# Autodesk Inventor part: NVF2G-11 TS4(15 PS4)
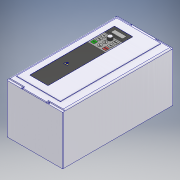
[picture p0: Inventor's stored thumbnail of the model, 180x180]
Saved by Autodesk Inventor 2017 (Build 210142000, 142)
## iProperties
Part Number: NVF2G-11 TS4(15 PS4)
Material: Типовые
Document SubType Name: Modeling
Designer: RSagdiev
Density: 1 g/cm^3
Appearance: По умолчанию
Author: RSagdiev
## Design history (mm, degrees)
sketch "Эскиз1"
  geometry: L1 (0, 0)-(44.679, 0) reference; L2 (0, 0)-(0, 56.035) reference; L3 (0, 0)-(378, 0); L4 (378, 0)-(378, 167.6); L5 (378, 167.6)-(0, 167.6); L6 (0, 167.6)-(0, 0)
  constraints: 12 end point, 3 horizontal, 2 parallel, 2 vertical, 1 perpendicular
  dimensions: "d0" = 378 distance of L5.end L4.end; "d1" = 167.6 distance of L4.end L3.end
extrude "Выдавливание1" new body sketch "Эскиз1" stored distance "d2" = 191; taper "d3" = 0 deg
sketch "Эскиз2"
  geometry: L1 (0, 0)-(0, 378) reference; L2 (191, 0)-(191, 378) reference; L3 (0, 378)-(55, 378); L4 (191, 378)-(191, 371); L5 (191, 0)-(136, 0); L6 (0, 0)-(0, 7); L7 (0, 378)-(191, 378) reference; L8 (0, 378)-(55, 378); L9 (55, 378)-(55, 371); L10 (55, 371)-(0, 371); L11 (0, 371)-(0, 378); L12 (191, 378)-(136, 378); L13 (136, 378)-(136, 371); L14 (136, 371)-(191, 371); L15 (191, 371)-(191, 378); L16 (0, 0)-(191, 0) reference; L17 (0, 0)-(55, 0); L18 (55, 0)-(55, 7); L19 (55, 7)-(0, 7); L20 (0, 7)-(0, 0); L21 (191, 0)-(136, 0); L22 (136, 0)-(136, 7); L23 (136, 7)-(191, 7); L24 (191, 7)-(191, 0); L25 (55, 378)-(136, 378); L26 (0, 371)-(0, 378); L27 (136, 378)-(191, 378); L28 (191, 371)-(191, 7); L29 (136, 0)-(55, 0); L30 (191, 7)-(191, 0); L31 (55, 0)-(0, 0); L32 (0, 7)-(0, 371); 1 further point
  constraints: 56 end point, 26 parallel, 13 perpendicular, 7 horizontal
  dimensions: "d4" = 55 distance of L9.end L10.end; "d5" = 7 distance of L3.end L9.end; "d6" = 55 distance of L4.end L13.end; "d7" = 7 distance of L13.end L12.end; "d8" = 55 distance of L6.end L18.end; "d9" = 7 distance of L18.end L17.end; "d10" = 55 distance of L22.end L23.end; "d11" = 7 distance of L5.end L22.end
extrude "Выдавливание2" new body sketch "Эскиз2" distance "d12" = 4; taper "d13" = 0 deg
chamfer "Фаска1" distance "d14" = 4; stored, may be unused: second distance "d15" = 2, angle "d16" = 45 deg
sketch "Эскиз3"
  geometry: L1 (160.042, 23.143)-(160.042, 365.729); L2 (12.485, 365.729)-(160.042, 365.729); L3 (10.042, 365.729)-(10.042, 23.143); L4 (10.042, 365.729)-(160.042, 365.729); L5 (10.042, 23.143)-(160.042, 23.143); L6 (55, 374)-(136, 374) reference; L7 (55, 0)-(136, 0) reference; L8 (0, 371)-(0, 7) reference; L9 (191, 7)-(191, 371) reference; 1 further point
  constraints: 11 end point, 2 perpendicular, 1 horizontal, 1 point on line
  dimensions: "d160" = 8.27064 distance between parallel lines of L4 L6; "d161" = 23.14275 distance between parallel lines of L7 L5; "d162" = 10.04205 distance between parallel lines of L8 L3; "d164" = 30.95795 distance between parallel lines of L9 L1
extrude "Выдавливание3" new body sketch "Эскиз3" distance "d17" = 2; taper "d18" = 0 deg
sketch "Эскиз4"
  geometry: L1 (91, 338)-(32, 338); L2 (30, 336)-(30, 50); L3 (32, 48)-(91, 48); L4 (93, 50)-(93, 336); L5 (0, 378)-(191, 378) reference; L6 (0, 371)-(0, 7) reference; A1 r 2 centre (32, 336) between (32, 338) and (30, 336); A2 r 2 centre (91, 336) between (93, 336) and (91, 338); A3 r 2 centre (91, 50) between (91, 48) and (93, 50); A4 r 2 centre (32, 50) between (30, 50) and (32, 48); 6 further points
  constraints: 8 end point, 8 point on circle, 8 tangent, 6 point on line, 4 centre point, 3 equal radius, 2 parallel, 1 horizontal, 1 perpendicular
  dimensions: "d20" = 63 distance of point (93, 48) point (30, 48); "d21" = 290 distance of point (30, 48) point (30, 338); "d24" = 2 radius of A1; "d165" = 40 distance between parallel lines of L5 L1; "d166" = 30 distance between parallel lines of L6 L2
extrude "Выдавливание4" cut sketch "Эскиз4" distance "d25" = 0.6; taper "d26" = 0 deg
sketch "Эскиз5"
  geometry: L1 (0, 378)-(191, 378) reference; L2 (0, 0)-(0, 378) reference; L3 (191, 378)-(191, 0) reference; L4 (0, 0)-(191, 0) reference; C1 r 2.5 at (50.5, 374.5); C2 r 2.5 at (140.5, 374.5); C3 r 2.5 at (50.5, 3.5); C4 r 2.5 at (140.5, 3.5); 1 further point
  constraints: 4 centre point
  dimensions: "d27" = 5 diameter of C1; "d28" = 3.5 distance from line of C1.centre L1; "d30" = 5 diameter of C2; "d31" = 3.5 distance from line of C2.centre L1; "d33" = 5 diameter of C3; "d34" = 3.5 distance from line of L4 C3.centre; "d36" = 5 diameter of C4; "d38" = 3.5 distance from line of C4.centre L4; "d169" = 90 distance of C1.centre C2.centre; "d170" = 50.5 distance from line of L3 C2.centre; "d171" = 50.5 distance from line of L2 C1.centre (derived); "d172" = 90 distance of C4.centre C3.centre (derived); "d173" = 50.5 distance from line of L3 C4.centre (derived)
extrude "Выдавливание5" cut sketch "Эскиз5" stored distance "d39" = 0.6; taper "d40" = 0 deg
sketch "Эскиз6"
  geometry: L1 (30, 247)-(30, 303); L2 (92.577, 245)-(32, 245); L3 (93, 336)-(93, 303); L4 (32, 338)-(91, 338); L5 (30, 247)-(30, 336); L6 (30, 303)-(93, 303); L7 (93, 336)-(93, 246.954); L8 (30, 303)-(30, 336); L9 (93, 303)-(93, 246.954); L10 (43.5, 314)-(79.5, 314); L11 (81.5, 316)-(81.5, 326); L12 (79.5, 328)-(43.5, 328); L13 (41.5, 326)-(41.5, 316); L14 (41.5, 314)-(81.5, 328); L15 (81.5, 314)-(41.5, 328); L16 (61.5, 291.5)-(61.5, 256.857); L17 (53.25, 291.5)-(53.25, 256.857); L18 (69.75, 256.857)-(69.75, 291.5); L19 (47, 298)-(36, 298); L20 (35, 297)-(35, 286); L21 (36, 285)-(47, 285); L22 (48, 286)-(48, 297); L23 (48, 298)-(35, 285); L24 (35, 298)-(48, 285); L25 (81.5, 316)-(81.5, 251.5); L26 (41.5, 291.5)-(88.409, 291.5); L27 (39.654, 274.179)-(85.729, 274.179); L28 (39.654, 256.857)-(84.963, 256.857); L29 (88, 286)-(88, 297); L30 (76, 285)-(87, 285); L31 (88, 298)-(75, 285); L32 (75, 298)-(88, 285); L33 (75, 297)-(75, 286); L34 (87, 298)-(76, 298); L35 (88, 268.679)-(88, 279.679); L36 (76, 267.679)-(87, 267.679); L37 (88, 280.679)-(75, 267.679); L38 (75, 280.679)-(88, 267.679); L39 (75, 279.679)-(75, 268.679); L40 (87, 280.679)-(76, 280.679); L41 (88, 251.357)-(88, 262.357); L42 (76, 250.357)-(87, 250.357); L43 (88, 263.357)-(75, 250.357); L44 (75, 263.357)-(88, 250.357); L45 (75, 262.357)-(75, 251.357); L46 (87, 263.357)-(76, 263.357); L47 (48, 251.357)-(48, 262.357); L48 (36, 250.357)-(47, 250.357); L49 (48, 263.357)-(35, 250.357); L50 (35, 263.357)-(48, 250.357); L51 (35, 262.357)-(35, 251.357); L52 (47, 263.357)-(36, 263.357); L53 (48, 268.679)-(48, 279.679); L54 (36, 267.679)-(47, 267.679); L55 (48, 280.679)-(35, 267.679); L56 (35, 280.679)-(48, 267.679); L57 (35, 279.679)-(35, 268.679); L58 (47, 280.679)-(36, 280.679); L59 (92.577, 245)-(32, 245); L60 (93, 334.729)-(93, 246.954); L61 (0, 378)-(191, 378) reference; L62 (0, 369)-(0, 9) reference; C1 r 6.5 at (61.5, 291.5); C2 r 6.5 at (61.5, 256.857); C3 r 6.5 at (61.5, 274.179); A1 r 2 centre (43.5, 326) between (43.5, 328) and (41.5, 326); A2 r 2 centre (79.5, 326) between (81.5, 326) and (79.5, 328); A3 r 2 centre (79.5, 316) between (79.5, 314) and (81.5, 316); A4 r 2 centre (43.5, 316) between (41.5, 316) and (43.5, 314); A5 r 8.25 centre (61.5, 291.5) between (69.75, 291.5) and (53.25, 291.5); A6 r 8.25 centre (61.5, 256.857) between (53.25, 256.857) and (69.75, 256.857); A7 r 1 centre (47, 297) between (48, 297) and (47, 298); A8 r 1 centre (47, 286) between (47, 285) and (48, 286); A9 r 1 centre (36, 286) between (35, 286) and (36, 285); A10 r 1 centre (36, 297) between (36, 298) and (35, 297); A11 r 1 centre (87, 286) between (87, 285) and (88, 286); A12 r 1 centre (87, 297) between (88, 297) and (87, 298); A13 r 1 centre (76, 297) between (76, 298) and (75, 297); A14 r 1 centre (76, 286) between (75, 286) and (76, 285); A15 r 1 centre (87, 268.679) between (87, 267.679) and (88, 268.679); A16 r 1 centre (87, 279.679) between (88, 279.679) and (87, 280.679); A17 r 1 centre (76, 279.679) between (76, 280.679) and (75, 279.679); A18 r 1 centre (76, 268.679) between (75, 268.679) and (76, 267.679); A19 r 1 centre (87, 251.357) between (87, 250.357) and (88, 251.357); A20 r 1 centre (87, 262.357) between (88, 262.357) and (87, 263.357); A21 r 1 centre (76, 262.357) between (76, 263.357) and (75, 262.357); A22 r 1 centre (76, 251.357) between (75, 251.357) and (76, 250.357); A23 r 1 centre (47, 251.357) between (47, 250.357) and (48, 251.357); A24 r 1 centre (47, 262.357) between (48, 262.357) and (47, 263.357); A25 r 1 centre (36, 262.357) between (36, 263.357) and (35, 262.357); A26 r 1 centre (36, 251.357) between (35, 251.357) and (36, 250.357); A27 r 1 centre (47, 268.679) between (47, 267.679) and (48, 268.679); A28 r 1 centre (47, 279.679) between (48, 279.679) and (47, 280.679); A29 r 1 centre (36, 279.679) between (36, 280.679) and (35, 279.679); A30 r 1 centre (36, 268.679) between (35, 268.679) and (36, 267.679); A31 r 2 centre (32, 336) between (32, 338) and (30, 336); A32 r 2 centre (91, 336) between (93, 336) and (91, 338); A33 r 2 centre (91.095, 246.344) between (92.577, 245) and (93, 246.954); A34 r 2 centre (32, 247) between (30, 247) and (32, 245); 15 further points
  constraints: 122 end point, 68 point on circle, 68 point on line, 66 tangent, 37 centre point, 21 equal radius, 15 midpoint, 15 parallel, 11 horizontal, 7 collinear, 7 perpendicular, 3 coincident, 2 vertical
  dimensions: "d43" = 35 distance between parallel lines of L4 L6; "d44" = 40 distance of L15.end L14.end; "d45" = 14 distance of L14.end L15.start; "d46" = 10 distance between parallel lines of L4 L12; "d47" = 2 radius of A1; "d48" = 11.5 distance between parallel lines of L8 L13; "d49" = 16.5 diameter of A6; "d50" = 31.5 distance between parallel lines of L1 L16; "d51" = 11.5 distance from line of L6 L16.start; "d52" = 11.85714 distance from line of L2 L16.end; "d53" = 13 diameter of C1; "d54" = 13 diameter of C2; "d55" = 13 diameter of C3; "d56" = 13 distance of L24.end L23.end; "d57" = 13 distance of L23.end L24.start; "d58" = 1 radius of A7 (derived); "d59" = 11.5 distance from line of L6 L26.start; "d60" = 11.5 distance from line of L5 L26.start; "d61" = 13 distance of L32.end L31.end; "d62" = 13 distance of L31.end L32.start; "d63" = 1 radius of A12 (derived); "d64" = 13 distance of L38.end L37.end; "d65" = 13 distance of L37.end L38.start; "d66" = 1 radius of A16 (derived); "d67" = 13 distance of L44.end L43.end; "d68" = 13 distance of L43.end L44.start; "d69" = 1 radius of A20 (derived); "d70" = 13 distance of L50.end L49.end; "d71" = 13 distance of L49.end L50.start; "d72" = 1 radius of A24 (derived); "d73" = 13 distance of L56.end L55.end; "d74" = 13 distance of L55.end L56.start; "d75" = 1 radius of A28 (derived); "d146" = 40 distance of point (81.5, 291.5) L26.start; "d147" = 4.32143 distance between parallel lines of L40 L30; "d148" = 4.32143 distance between parallel lines of L46 L36; "d149" = 93 distance between parallel lines of L2 L4; "d150" = 63 distance between parallel lines of L60 L1; "d151" = 2 radius of A31; "d152" = 2 radius of A32; "d153" = 2 radius of A33; "d154" = 2 radius of A34; "d167" = 40 distance between parallel lines of L4 L61 (derived); "d168" = 30 distance between parallel lines of L62 L5 (derived)
extrude "Выдавливание6" new body sketch "Эскиз6" distance "d76" = 0.3; taper "d77" = 0 deg
extrude "Выдавливание7" new body sketch "Эскиз6" distance "d78" = 0.6; taper "d79" = 0 deg
sketch "Эскиз7"
  geometry: L1 (30, 303)-(93, 303) reference; L2 (30, 303)-(93, 303); L3 (93, 303)-(93, 303.1); L4 (93, 303.1)-(30, 303.1); L5 (30, 303.1)-(30, 303); 4 further points; 1 other entity
  constraints: 8 end point, 2 parallel, 1 horizontal, 1 perpendicular, 2 other
  dimensions: "d80" = 0.1 distance of L3.end L2.end
extrude "Выдавливание8" cut sketch "Эскиз7" distance "d81" = 0.3; taper "d82" = 0 deg
sketch "Эскиз8" dims "d91" = 10
  geometry: L1 (30, 303.1)-(93, 303.1) reference; C1 r 1 at (38, 308.1); C2 r 1 at (45.75, 308.1); C3 r 1 at (53.5, 308.1); C4 r 1 at (61.25, 308.1); C5 r 1 at (69, 308.1); C6 r 1 at (76.75, 308.1); C7 r 1 at (84.5, 308.1); 4 further points; 1 other entity
  constraints: 7 centre point, 1 horizontal, 13 other
  dimensions: "d83" = 2 diameter of C1; "d84" = 5 distance from line of C1.centre L1; "d85" = 8 dimension on C1.centre; "d88" = 7.75 distance of C1.centre C2.centre
extrude "Выдавливание9" join sketch "Эскиз8" distance "d93" = 0.3; taper "d94" = 0 deg
sketch "Эскиз9"
  geometry: C1 r 6.5 at (0, 0) reference; C2 r 7.5 at (0, 0); 1 further point
  constraints: 1 centre point, 1 coincident
  dimensions: "d95" = 15 diameter of C2
extrude "Выдавливание10" join sketch "Эскиз9" distance "d96" = 9.4; taper "d97" = -3 deg
sketch "Эскиз10"
  geometry: L1 (0, 7.331)-(0.619, 6.259); L2 (0.619, 6.259)-(-0.619, 6.259); L3 (-0.619, 6.259)-(0, 7.331); 2 further points
  constraints: 6 end point, 7 other
sketch "Эскиз11"
  geometry: L1 (0, 7.917)-(0.884, 6.386); L2 (0.884, 6.386)-(-0.884, 6.386); L3 (-0.884, 6.386)-(0, 7.917); 2 further points
  constraints: 6 end point, 7 other
feature "Лофт1" sketch "Эскиз10", "Эскиз11" dims "d98" = 0, "d99" = 90 deg, "d100" = 0, "d101" = 90 deg
sketch "Эскиз12"
  geometry: L1 (38.421, 293.217)-(44.641, 293.217); L2 (44.641, 293.217)-(44.641, 289.717); L3 (44.641, 289.717)-(38.421, 289.717); L4 (38.421, 289.717)-(38.421, 293.217); L5 (37.471, 276.118)-(46.326, 276.118); L6 (46.326, 276.118)-(46.326, 272.488); L7 (46.326, 272.488)-(37.471, 272.488); L8 (37.471, 272.488)-(37.471, 276.118); L9 (37.115, 258.782)-(46.472, 258.782); L10 (46.472, 258.782)-(46.472, 255.208); L11 (46.472, 255.208)-(37.115, 255.208); L12 (37.115, 255.208)-(37.115, 258.782); L13 (75.944, 258.782)-(87.496, 258.782); L14 (87.496, 258.782)-(87.496, 255.135); L15 (87.496, 255.135)-(75.944, 255.135); L16 (75.944, 255.135)-(75.944, 258.782); L17 (77.725, 276)-(85.919, 276); L18 (85.919, 276)-(85.919, 272.375); L19 (85.919, 272.375)-(77.725, 272.375); L20 (77.725, 272.375)-(77.725, 276); L21 (75.825, 293.336)-(88.875, 293.336); L22 (88.875, 293.336)-(88.875, 289.711); L23 (88.875, 289.711)-(75.825, 289.711); L24 (75.825, 289.711)-(75.825, 293.336); 1 further point
  constraints: 12 other
feature "Рельеф1" dims "d105" = 0.1, "d106" = 0
feature "Рельеф2" dims "d107" = 0.1, "d108" = 0
feature "Рельеф3" dims "d109" = 0.1, "d110" = 0
feature "Рельеф4" dims "d111" = 0.1, "d112" = 0
feature "Рельеф5" dims "d113" = 0.1, "d114" = 0
feature "Рельеф6" dims "d115" = 0.1, "d116" = 0
sketch "Эскиз13"
  geometry: L1 (-3.144, -2.347)-(-0.04, 3.728); L2 (-0.04, 3.728)-(3.298, -2.347); L3 (3.298, -2.347)-(2.096, -2.347); L4 (2.096, -2.347)-(-0.04, 1.541); L5 (-0.04, 1.541)-(-2.027, -2.347); L6 (-2.027, -2.347)-(-3.144, -2.347); L7 (-9.387, -8.657)-(8.031, -8.657); L8 (-3.144, -14.967)-(-0.04, -21.041); L9 (-0.04, -21.041)-(3.298, -14.967); L10 (3.298, -14.967)-(2.096, -14.967); L11 (2.096, -14.967)-(-0.04, -18.855); L12 (-0.04, -18.855)-(-2.027, -14.967); L13 (-2.027, -14.967)-(-3.144, -14.967); 1 further point
  constraints: 26 end point, 6 symmetric about line, 2 horizontal, 2 parallel, 2 point on line, 1 collinear
feature "Рельеф7" dims "d117" = 0.1, "d118" = 0
feature "Рельеф8" dims "d119" = 0.1, "d120" = 0
sketch "Эскиз14"
  geometry: L1 (58.847, 155.147)-(67.143, 140.777); L2 (67.143, 140.777)-(50.55, 140.777); L3 (50.55, 140.777)-(58.847, 155.147); L4 (65.716, 141.601)-(58.847, 153.499); L5 (58.847, 153.499)-(51.977, 141.601); L6 (51.977, 141.601)-(65.716, 141.601); L7 (58.02, 149.832)-(57.079, 146.022); L8 (57.079, 146.022)-(59.5, 146.192); L9 (59.5, 146.192)-(58.459, 143.876); L10 (58.459, 143.876)-(57.51, 144.303); L11 (57.51, 144.303)-(57.666, 142.072); L12 (57.666, 142.072)-(60.137, 143.122); L13 (60.137, 143.122)-(59.456, 143.428); L14 (59.456, 143.428)-(61.385, 147.064); L15 (61.385, 147.064)-(58.23, 146.881); L16 (58.23, 146.881)-(59.796, 149.832); L17 (59.796, 149.832)-(58.02, 149.832); 2 further points
  constraints: 34 end point, 2 perpendicular, 2 point on line, 1 parallel, 9 other
extrude "Выдавливание11" cut sketch "Эскиз14" distance "d121" = 0.8; taper "d122" = 0 deg
extrude "Выдавливание12" join sketch "Эскиз14" stored distance "d123" = 0.05; taper "d124" = 0 deg
sketch "Эскиз15"
  geometry: L1 (32.937, 312.698)-(57.63, 312.698); L2 (57.63, 312.698)-(57.63, 309.81); L3 (57.63, 309.81)-(32.937, 309.81); L4 (32.937, 309.81)-(32.937, 312.698); L5 (58.162, 311.617)-(88.881, 311.617); L6 (88.881, 311.617)-(88.881, 307.704); L7 (88.881, 307.704)-(58.162, 307.704); L8 (58.162, 307.704)-(58.162, 311.617); L9 (30, 303.1)-(93, 303.1) reference; C1 r 1 at (38, 308.1) reference; 7 further points; 2 other entities
  constraints: 6 other
  dimensions: "d155" = 0.71019 distance edge to line of C1 L3; "d156" = 2.93695 dimension on L4; "d157" = 4.60387 distance between parallel lines of L9 L7; "d158" = 4.11868 dimension on L6
feature "Рельеф9" sketch "Эскиз15" dims "d125" = 0.1, "d126" = 0
sketch "Эскиз17"
  geometry: L1 (54.534, 359)-(54.534, 352.001); L2 (54.534, 352.001)-(52.465, 352.001); L3 (52.465, 352.001)-(52.465, 359); L4 (52.465, 359)-(54.534, 359); 1 further point
  constraints: 2 other
feature "Рельеф10" sketch "Эскиз17" dims "d144" = 0.1, "d145" = 0
sketch "Эскиз19" dims "d179" = 10
  geometry: L1 (113.24, 333.958)-(134.375, 351.485); L2 (114.525, 332.409)-(135.66, 349.935); L3 (133.09, 353.034)-(111.955, 335.508); L4 (167.6, 371)-(167.6, 7) reference; L5 (113.24, 323.958)-(134.375, 341.485); L6 (114.525, 322.409)-(135.66, 339.935); L7 (133.09, 343.034)-(111.955, 325.508); L8 (113.24, 313.958)-(134.375, 331.485); L9 (114.525, 312.409)-(135.66, 329.935); L10 (133.09, 333.034)-(111.955, 315.508); L11 (113.24, 303.958)-(134.375, 321.485); L12 (114.525, 302.409)-(135.66, 319.935); L13 (133.09, 323.034)-(111.955, 305.508); L14 (113.24, 293.958)-(134.375, 311.485); L15 (114.525, 292.409)-(135.66, 309.935); L16 (133.09, 313.034)-(111.955, 295.508); L17 (113.24, 283.958)-(134.375, 301.485); L18 (114.525, 282.409)-(135.66, 299.935); L19 (133.09, 303.034)-(111.955, 285.508); L20 (113.24, 273.958)-(134.375, 291.485); L21 (114.525, 272.409)-(135.66, 289.935); L22 (133.09, 293.034)-(111.955, 275.508); L23 (113.24, 263.958)-(134.375, 281.485); L24 (114.525, 262.409)-(135.66, 279.935); L25 (133.09, 283.034)-(111.955, 265.508); L26 (113.24, 253.958)-(134.375, 271.485); L27 (114.525, 252.409)-(135.66, 269.935); L28 (133.09, 273.034)-(111.955, 255.508); L29 (113.24, 243.958)-(134.375, 261.485); L30 (114.525, 242.409)-(135.66, 259.935); L31 (133.09, 263.034)-(111.955, 245.508); A1 r 2.013 centre (113.24, 333.958) between (111.955, 335.508) and (114.525, 332.409); A2 r 2.013 centre (134.375, 351.485) between (135.66, 349.935) and (133.09, 353.034); A3 r 2.013 centre (113.24, 323.958) between (111.955, 325.508) and (114.525, 322.409); A4 r 2.013 centre (134.375, 341.485) between (135.66, 339.935) and (133.09, 343.034); A5 r 2.013 centre (113.24, 313.958) between (111.955, 315.508) and (114.525, 312.409); A6 r 2.013 centre (134.375, 331.485) between (135.66, 329.935) and (133.09, 333.034); A7 r 2.013 centre (113.24, 303.958) between (111.955, 305.508) and (114.525, 302.409); A8 r 2.013 centre (134.375, 321.485) between (135.66, 319.935) and (133.09, 323.034); A9 r 2.013 centre (113.24, 293.958) between (111.955, 295.508) and (114.525, 292.409); A10 r 2.013 centre (134.375, 311.485) between (135.66, 309.935) and (133.09, 313.034); A11 r 2.013 centre (113.24, 283.958) between (111.955, 285.508) and (114.525, 282.409); A12 r 2.013 centre (134.375, 301.485) between (135.66, 299.935) and (133.09, 303.034); A13 r 2.013 centre (113.24, 273.958) between (111.955, 275.508) and (114.525, 272.409); A14 r 2.013 centre (134.375, 291.485) between (135.66, 289.935) and (133.09, 293.034); A15 r 2.013 centre (113.24, 263.958) between (111.955, 265.508) and (114.525, 262.409); A16 r 2.013 centre (134.375, 281.485) between (135.66, 279.935) and (133.09, 283.034); A17 r 2.013 centre (113.24, 253.958) between (111.955, 255.508) and (114.525, 252.409); A18 r 2.013 centre (134.375, 271.485) between (135.66, 269.935) and (133.09, 273.034); A19 r 2.013 centre (113.24, 243.958) between (111.955, 245.508) and (114.525, 242.409); A20 r 2.013 centre (134.375, 261.485) between (135.66, 259.935) and (133.09, 263.034); 13 further points
  constraints: 80 end point, 40 point on circle, 20 centre point, 4 tangent, 1 midpoint, 1 parallel, 1 vertical, 108 other
  dimensions: "d176" = 10 distance of L2.start L6.start
extrude "Выдавливание14" cut sketch "Эскиз19" distance "d181" = 10; taper "d182" = 0 deg
sketch "Эскиз20" dims "d191" = 10, "d198" = 10
  geometry: L1 (167.6, 2)-(0, 2) reference; L2 (0, 378)-(0, 0) reference; C1 r 2 at (15, 132); C2 r 2 at (20, 132); C3 r 2 at (25, 132); C4 r 2 at (30, 132); C5 r 2 at (35, 132); C6 r 2 at (40, 132); C7 r 2 at (45, 132); C8 r 2 at (50, 132); C9 r 2 at (55, 132); C10 r 2 at (60, 132); C11 r 2 at (65, 132); C12 r 2 at (70, 132); C13 r 2 at (70, 127); C14 r 2 at (65, 127); C15 r 2 at (60, 127); C16 r 2 at (55, 127); C17 r 2 at (15, 127); C18 r 2 at (20, 127); C19 r 2 at (25, 127); C20 r 2 at (30, 127); C21 r 2 at (35, 127); C22 r 2 at (40, 127); C23 r 2 at (45, 127); C24 r 2 at (50, 127); C25 r 2 at (70, 122); C26 r 2 at (65, 122); C27 r 2 at (60, 122); C28 r 2 at (55, 122); C29 r 2 at (15, 122); C30 r 2 at (20, 122); C31 r 2 at (25, 122); C32 r 2 at (30, 122); C33 r 2 at (35, 122); C34 r 2 at (40, 122); C35 r 2 at (45, 122); C36 r 2 at (50, 122); C37 r 2 at (70, 117); C38 r 2 at (65, 117); C39 r 2 at (60, 117); C40 r 2 at (55, 117); C41 r 2 at (15, 117); C42 r 2 at (20, 117); C43 r 2 at (25, 117); C44 r 2 at (30, 117); C45 r 2 at (35, 117); C46 r 2 at (40, 117); C47 r 2 at (45, 117); C48 r 2 at (50, 117); C49 r 2 at (70, 112); C50 r 2 at (65, 112); C51 r 2 at (60, 112); C52 r 2 at (55, 112); C53 r 2 at (15, 112); C54 r 2 at (20, 112); C55 r 2 at (25, 112); C56 r 2 at (30, 112); C57 r 2 at (35, 112); C58 r 2 at (40, 112); C59 r 2 at (45, 112); C60 r 2 at (50, 112); C61 r 2 at (70, 107); C62 r 2 at (65, 107); C63 r 2 at (60, 107); C64 r 2 at (55, 107)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; 1 further point
  constraints: 240 centre point, 1 horizontal, 1 vertical, 478 other
  dimensions: "d183" = 4 diameter of C1; "d184" = 15 distance from line of L2 C1.centre; "d185" = 130 distance from line of L1 C1.centre; "d188" = 5 distance of C1.centre C2.centre; "d195" = 5 distance of C12.centre C13.centre
extrude "Выдавливание15" cut sketch "Эскиз20" distance "d200" = 15; taper "d201" = 0 deg
fillet "Сопряжение3" dims "d202" = 5
fillet "Сопряжение4" dims "d203" = 2
node "Твердое тело1"
pattern_circular "Круговой массив1" dims angle "d103" = 360 deg
node "Твердое тело2"
node "Твердое тело3"
node "Твердое тело4"
node "Твердое тело5"
